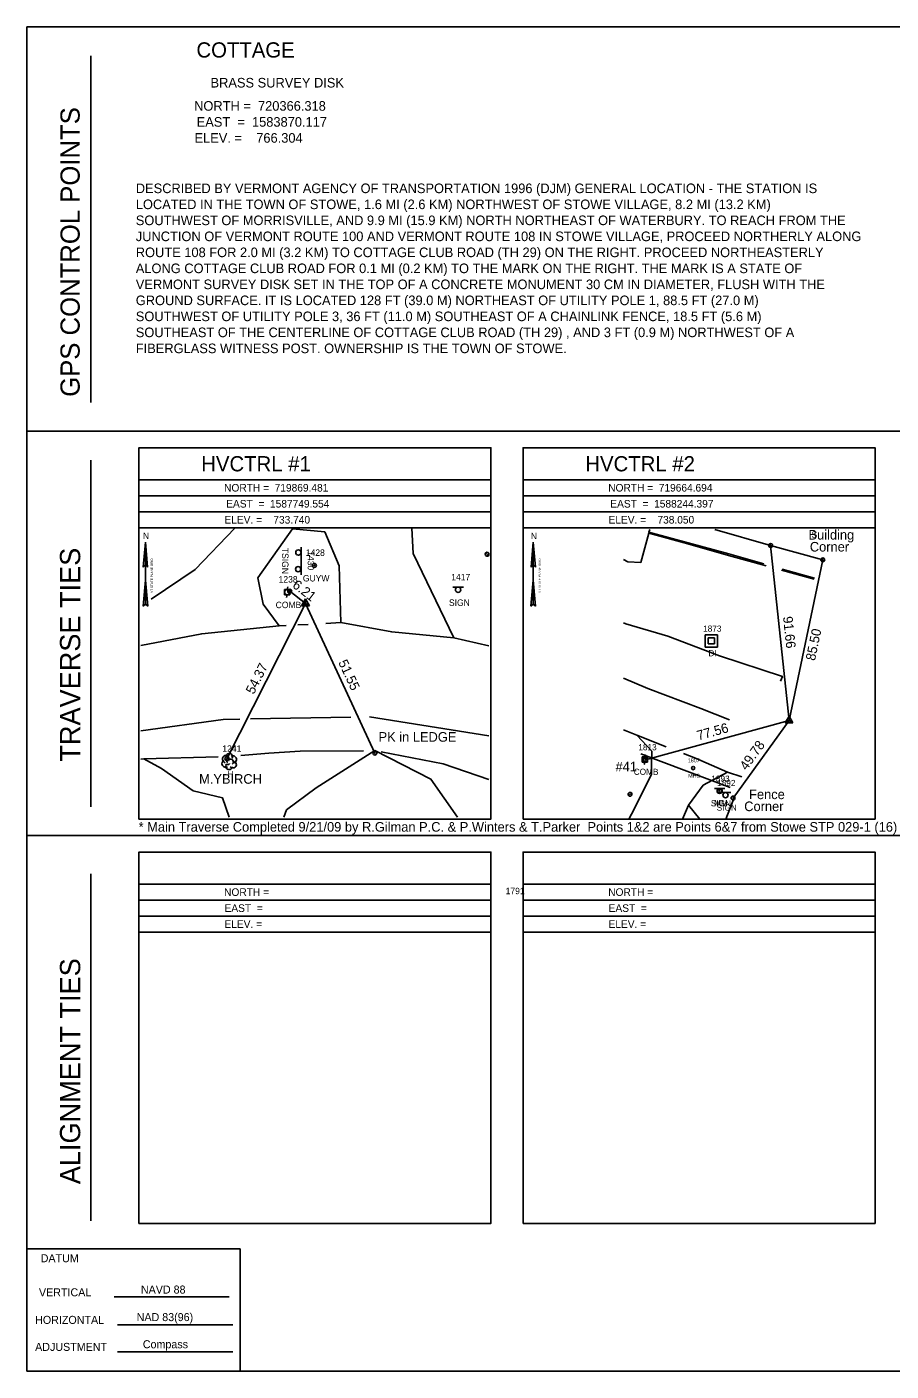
# Model space of a CAD drawing. Extents: x 1586965 to 1590952, y 716317 to 720029.
# Drawn here: x 1590312.2 to 1590582.2, y 716317.4 to 716737.4 of the extents above; entities that cross this region are included whole.
import ezdxf

# ---------------------------------------------------------------- set-up
doc = ezdxf.new("R2010")
doc.units = 0
for name, color, linetype in [('C_C', 7, 'Continuous'), ('CBP', 7, 'Continuous'), ('CPSM', 7, 'Continuous'), ('D_A', 7, 'Continuous'), ('D_I', 7, 'Continuous'), ('DCP', 7, 'Continuous'), ('Default', 7, 'Continuous'), ('DS', 7, 'Continuous'), ('L_A', 7, 'Continuous'), ('L_C', 7, 'Continuous'), ('L_I', 7, 'Continuous'), ('LARO', 7, 'Continuous'), ('LAWA', 7, 'Continuous'), ('LBC', 7, 'Continuous'), ('LFNC', 7, 'Continuous'), ('LTD', 7, 'Continuous'), ('NBL1', 7, 'Continuous'), ('NBL2', 7, 'Continuous'), ('NNA_P', 7, 'Continuous'), ('PET', 7, 'Continuous'), ('RDG', 7, 'Continuous'), ('RDP', 7, 'Continuous'), ('RSW', 7, 'Continuous'), ('S_A', 7, 'Continuous'), ('S_I', 7, 'Continuous'), ('SRM', 7, 'Continuous'), ('SSGN', 7, 'Continuous'), ('U_A', 7, 'Continuous'), ('U_C', 7, 'Continuous'), ('U_I', 7, 'Continuous'), ('UP', 7, 'Continuous'), ('UPGW', 7, 'Continuous'), ('USMH', 7, 'Continuous'), ('UWV', 7, 'Continuous')]:
    doc.layers.add(name, color=color, linetype=linetype)

msp = doc.modelspace()

# ---------------------------------------------------------------- linework, layer by layer
at = {"layer": 'CBP'}
for centre, radius in [((1590544.56, 716575.34), 0.6), ((1590544.56, 716575.34), 0.08), ((1590560.84, 716570.85), 0.6), ((1590560.84, 716570.85), 0.08), ((1590394.3, 716561.05), 0.625), ((1590394.3, 716561.05), 0.0833), ((1590374.69, 716508.7), 0.625), ((1590374.69, 716508.7), 0.0833), ((1590420.91, 716510.48), 0.625), ((1590420.91, 716510.48), 0.0833), ((1590505.42, 716508.32), 0.6), ((1590505.42, 716508.32), 0.08), ((1590532.82, 716496.43), 0.6), ((1590532.82, 716496.43), 0.08)]:
    msp.add_circle(centre, radius, dxfattribs=at)
at = {"layer": 'CPSM'}
for p, q in [((1590397.95, 716556.51), (1590399.2, 716558.68)), ((1590400.45, 716556.51), (1590399.2, 716558.68)), ((1590399.2, 716557.24), (1590399.2, 716558.68)), ((1590397.95, 716556.51), (1590399.2, 716557.24)), ((1590397.95, 716556.51), (1590400.45, 716556.51)), ((1590399.2, 716557.24), (1590399.2, 716557.24)), ((1590399.2, 716557.24), (1590400.45, 716556.51)), ((1590549.1, 716519.95), (1590550.3, 716522.03)), ((1590549.1, 716519.95), (1590550.3, 716520.64)), ((1590551.5, 716519.95), (1590550.3, 716522.03)), ((1590550.3, 716520.64), (1590550.3, 716522.03)), ((1590550.3, 716520.64), (1590550.3, 716520.64)), ((1590550.3, 716520.64), (1590551.5, 716519.95)), ((1590549.1, 716519.95), (1590551.5, 716519.95))]:
    msp.add_line(p, q, dxfattribs=at)
at = {"layer": 'DCP'}
msp.add_lwpolyline([(1590531.89, 716499.7), (1590504.01, 716510.18)], dxfattribs=at)
at = {"layer": 'Default'}
for p, q in [((1590550.3, 716520.64), (1590544.56, 716575.34)), ((1590560.84, 716570.85), (1590550.3, 716520.64)), ((1590399.2, 716557.24), (1590394.3, 716561.05)), ((1590374.69, 716508.7), (1590399.2, 716557.24)), ((1590399.2, 716557.24), (1590420.91, 716510.48)), ((1590505.42, 716508.32), (1590550.3, 716520.64)), ((1590550.3, 716520.64), (1590532.82, 716496.43))]:
    msp.add_line(p, q, dxfattribs=at)
at = {"layer": 'DS'}
for p, q in [((1590524.13, 716547.43), (1590527.97, 716547.43)), ((1590524.13, 716543.59), (1590524.13, 716547.43)), ((1590525.09, 716544.55), (1590525.09, 716546.47)), ((1590525.09, 716546.47), (1590527.01, 716546.47)), ((1590526.05, 716545.51), (1590526.05, 716545.51)), ((1590526.05, 716545.51), (1590526.05, 716545.51)), ((1590527.01, 716546.47), (1590527.01, 716544.55)), ((1590527.97, 716547.43), (1590527.97, 716543.59)), ((1590527.97, 716543.59), (1590524.13, 716543.59)), ((1590527.01, 716544.55), (1590525.09, 716544.55))]:
    msp.add_line(p, q, dxfattribs=at)
at = {"layer": 'LARO'}
for points in [[(1590347.78, 716508.6), (1590348.75, 716508.72), (1590354.22, 716505.67), (1590364.15, 716498.63), (1590373.3, 716496.5), (1590375.4, 716490.46)], [(1590392.42, 716490.46), (1590393.26, 716492.73), (1590402.53, 716499.63), (1590420.9, 716511.25), (1590438.43, 716502.34), (1590446.73, 716490.46)]]:
    msp.add_lwpolyline(points, dxfattribs=at)
at = {"layer": 'LAWA'}
for points in [[(1590347.78, 716508.6), (1590348.75, 716508.72), (1590371.97, 716509.25)], [(1590379.08, 716509.66), (1590387.8, 716510.41), (1590397.54, 716511.06), (1590417.31, 716511.22)], [(1590422.83, 716510.88), (1590442.3, 716507.07), (1590456.56, 716502.18)]]:
    msp.add_lwpolyline(points, dxfattribs=at)
at = {"layer": 'LBC'}
msp.add_line((1590544.56, 716575.34), (1590560.84, 716570.85), dxfattribs=at)
msp.add_lwpolyline([(1590527.08, 716580.33), (1590544.56, 716575.34)], dxfattribs=at)
at = {"layer": 'LFNC'}
msp.add_lwpolyline([(1590533.06, 716496.24), (1590530.56, 716489.86)], dxfattribs=at)
at = {"layer": 'LTD'}
msp.add_line((1590375.38, 716507.88), (1590375.38, 716507.88), dxfattribs=at)
msp.add_line((1590375.38, 716507.88), (1590375.38, 716507.88), dxfattribs=at)
msp.add_arc((1590375.42, 716509.31), 1.05, 335.5272, 180.9563, dxfattribs=at)
for centre, major_axis, ratio, start_param, end_param in [((1590374.29, 716507.17), (0.58, -1.04), 0.959034, 3.141593, 6.283185), ((1590374.58, 716508.54), (1.21, -0.51), 0.895232, 1.570796, 4.712389), ((1590375.17, 716508.34), (-0.208, -0.792), 0.645439, 3.141593, 6.283185), ((1590375.88, 716507.71), (-0.5, 0.667), 0.989748, 3.141593, 6.283185), ((1590376.38, 716507.04), (-1.09, 0.79), 0.841452, 1.570796, 4.712389), ((1590376.42, 716508.46), (-1.14, -0.48), 0.949671, 1.570796, 4.712389), ((1590375.38, 716506.38), (0.26, 1.06), 0.942809, 1.570796, 4.712389), ((1590374.92, 716507.13), (-0.625, -0.083), 0.423636, 0, 3.141593)]:
    msp.add_ellipse(centre, major_axis=major_axis, ratio=ratio, start_param=start_param, end_param=end_param, dxfattribs=at)
at = {"layer": 'NBL1'}
msp.add_lwpolyline([(1590312.19, 716317.36), (1590952.19, 716317.36), (1590952.19, 716737.36), (1590312.19, 716737.36)], close=True, dxfattribs=at)
at = {"layer": 'NBL2'}
for p, q in [((1590332.19, 716620.03), (1590332.19, 716728.36)), ((1590312.19, 716611.03), (1590952.19, 716611.03)), ((1590332.19, 716493.7), (1590332.19, 716602.03)), ((1590457.19, 716595.86), (1590347.19, 716595.86)), ((1590577.19, 716595.86), (1590467.19, 716595.86)), ((1590457.19, 716590.86), (1590347.19, 716590.86)), ((1590577.19, 716590.86), (1590467.19, 716590.86)), ((1590457.19, 716585.86), (1590347.19, 716585.86)), ((1590577.19, 716585.86), (1590467.19, 716585.86)), ((1590457.19, 716580.86), (1590347.19, 716580.86)), ((1590577.19, 716580.86), (1590467.19, 716580.86)), ((1590312.19, 716484.7), (1590952.19, 716484.7)), ((1590332.19, 716364.36), (1590332.19, 716472.7)), ((1590457.19, 716469.53), (1590347.19, 716469.53)), ((1590577.19, 716469.53), (1590467.19, 716469.53)), ((1590457.19, 716464.53), (1590347.19, 716464.53)), ((1590577.19, 716464.53), (1590467.19, 716464.53)), ((1590457.19, 716459.53), (1590347.19, 716459.53)), ((1590577.19, 716459.53), (1590467.19, 716459.53)), ((1590457.19, 716454.53), (1590347.19, 716454.53)), ((1590577.19, 716454.53), (1590467.19, 716454.53)), ((1590378.86, 716355.62), (1590312.19, 716355.62)), ((1590378.86, 716355.62), (1590378.86, 716317.36)), ((1590378.86, 716355.62), (1590378.86, 716317.36)), ((1590339.43, 716340.59), (1590375.43, 716340.56)), ((1590340.54, 716331.82), (1590376.54, 716331.82)), ((1590340.54, 716323.38), (1590376.54, 716323.35))]:
    msp.add_line(p, q, dxfattribs=at)
for points in [[(1590347.19, 716489.86), (1590457.19, 716489.86), (1590457.19, 716605.86), (1590347.19, 716605.86)], [(1590467.19, 716489.86), (1590577.19, 716489.86), (1590577.19, 716605.86), (1590467.19, 716605.86)], [(1590347.19, 716363.53), (1590457.19, 716363.53), (1590457.19, 716479.53), (1590347.19, 716479.53)], [(1590467.19, 716363.53), (1590577.19, 716363.53), (1590577.19, 716479.53), (1590467.19, 716479.53)]]:
    msp.add_lwpolyline(points, close=True, dxfattribs=at)
at = {"layer": 'NNA_P'}
for p, q in [((1590348.54, 716568.55), (1590349.23, 716576.34)), ((1590349.23, 716556.97), (1590349.23, 716576.34)), ((1590349.92, 716568.55), (1590349.23, 716576.34)), ((1590469.69, 716568.55), (1590470.39, 716576.34)), ((1590470.39, 716556.97), (1590470.39, 716576.34)), ((1590471.08, 716568.55), (1590470.39, 716576.34)), ((1590348.54, 716568.55), (1590349.23, 716569.31)), ((1590349.93, 716568.55), (1590349.23, 716569.31)), ((1590469.69, 716568.55), (1590470.39, 716569.31)), ((1590471.08, 716568.55), (1590470.39, 716569.31)), ((1590349.24, 716564.49), (1590348.51, 716556.33)), ((1590349.23, 716564.49), (1590349.95, 716556.33)), ((1590470.39, 716564.49), (1590469.67, 716556.33)), ((1590470.39, 716564.49), (1590471.11, 716556.33)), ((1590349.23, 716556.97), (1590348.51, 716556.33)), ((1590349.23, 716556.97), (1590349.95, 716556.33)), ((1590470.39, 716556.97), (1590469.67, 716556.33)), ((1590470.39, 716556.97), (1590471.11, 716556.33))]:
    msp.add_line(p, q, dxfattribs=at)
at = {"layer": 'PET'}
for points in [[(1590351.06, 716558.59), (1590364.78, 716567.86), (1590377.17, 716580.69)], [(1590391, 716550.19), (1590386.04, 716557.02), (1590384.37, 716565.19), (1590395.18, 716580.56), (1590405.23, 716579.6), (1590409.8, 716568.93), (1590410.24, 716551.25)], [(1590432.44, 716580.69), (1590432.88, 716572.84), (1590445.62, 716546.49)], [(1590347.78, 716544.1), (1590366.85, 716547.73), (1590391, 716550.19), (1590393.23, 716550.32)], [(1590396.85, 716550.51), (1590400.06, 716550.69)], [(1590405.57, 716550.99), (1590410.24, 716551.25), (1590426.21, 716548.33), (1590445.62, 716546.49), (1590456.56, 716543.97)], [(1590498.55, 716533.92), (1590506.19, 716530.66), (1590522.72, 716524.42), (1590531.67, 716520.9)], [(1590347.78, 716517.39), (1590373.53, 716520.96), (1590378.69, 716521.06)], [(1590382.05, 716521.12), (1590413.4, 716521.7)], [(1590419.24, 716521.8), (1590456.56, 716515.85)], [(1590498.55, 716517.77), (1590502.72, 716516.03), (1590511.9, 716512.47)], [(1590502.72, 716516.03), (1590507.43, 716511.07), (1590507.26, 716503.53), (1590501.04, 716491.38), (1590500.29, 716489.86)], [(1590517.32, 716510.36), (1590521.07, 716508.9), (1590531.09, 716504.54), (1590535.58, 716503)], [(1590517.03, 716489.86), (1590518.92, 716494.15), (1590523.51, 716500.47), (1590531.09, 716504.54)]]:
    msp.add_lwpolyline(points, dxfattribs=at)
at = {"layer": 'RDG'}
for points in [[(1590498.55, 716570.92), (1590499.93, 716570.23), (1590504.03, 716570.03)], [(1590498.55, 716551.11), (1590499.34, 716550.88)], [(1590522.42, 716489.86), (1590518.92, 716494.15)]]:
    msp.add_lwpolyline(points, dxfattribs=at)
at = {"layer": 'RDP'}
for points in [[(1590504.03, 716570.03), (1590506.46, 716579.21), (1590518.69, 716575.88), (1590531.36, 716572.16), (1590543.17, 716568.94)], [(1590547.99, 716567.62), (1590558.2, 716564.83)], [(1590499.34, 716550.88), (1590512.45, 716547), (1590528.53, 716540.88), (1590548.23, 716534.44), (1590547.61, 716532.89)]]:
    msp.add_lwpolyline(points, dxfattribs=at)
at = {"layer": 'RSW'}
for points in [[(1590506.78, 716580.33), (1590506.49, 716579.44), (1590518.76, 716576.18), (1590531.47, 716572.69), (1590542.47, 716569.59)], [(1590548.2, 716567.98), (1590558.29, 716565.14)]]:
    msp.add_lwpolyline(points, dxfattribs=at)
at = {"layer": 'SRM'}
msp.add_lwpolyline([(1590528.02, 716499.24), (1590529.22, 716499.24), (1590529.22, 716498.04), (1590528.02, 716498.04)], close=True, dxfattribs=at)
msp.add_circle((1590528.62, 716498.64), 0.08, dxfattribs=at)
at = {"layer": 'SSGN'}
for p, q in [((1590397.84, 716574.8), (1590397.84, 716566.2)), ((1590396.94, 716570.77), (1590396.94, 716570.77)), ((1590445.27, 716562.32), (1590448.6, 716562.32)), ((1590446.92, 716561.49), (1590446.92, 716561.49)), ((1590527.05, 716499.45), (1590530.25, 716499.45)), ((1590528.63, 716498.65), (1590528.63, 716498.65)), ((1590528.87, 716498.1), (1590532.07, 716498.1)), ((1590530.45, 716497.3), (1590530.45, 716497.3))]:
    msp.add_line(p, q, dxfattribs=at)
for centre, radius in [((1590397.01, 716573.13), 0.833), ((1590396.94, 716567.92), 0.833), ((1590446.92, 716561.49), 0.833), ((1590528.63, 716498.65), 0.8), ((1590530.45, 716497.3), 0.8)]:
    msp.add_circle(centre, radius, dxfattribs=at)
at = {"layer": 'UP'}
for p, q in [((1590393.77, 716562.42), (1590393.52, 716561.59)), ((1590392.69, 716559.92), (1590392.69, 716561.59)), ((1590392.69, 716561.59), (1590394.36, 716561.59)), ((1590394.36, 716559.92), (1590392.69, 716559.92)), ((1590393.27, 716559.09), (1590393.52, 716559.92)), ((1590393.52, 716560.75), (1590393.52, 716560.75)), ((1590394.36, 716561.59), (1590394.36, 716559.92)), ((1590504.47, 716507.66), (1590504.47, 716509.26)), ((1590504.47, 716509.26), (1590506.07, 716509.26)), ((1590506.07, 716507.66), (1590504.47, 716507.66)), ((1590505.03, 716506.86), (1590505.27, 716507.66)), ((1590505.51, 716510.06), (1590505.27, 716509.26)), ((1590505.27, 716508.46), (1590505.27, 716508.46)), ((1590506.07, 716509.26), (1590506.07, 716507.66))]:
    msp.add_line(p, q, dxfattribs=at)
for centre, radius in [((1590393.52, 716560.75), 0.833), ((1590505.27, 716508.46), 0.8)]:
    msp.add_circle(centre, radius, dxfattribs=at)
at = {"layer": 'UPGW'}
for centre, radius in [((1590402.02, 716569.09), 0.625), ((1590402.02, 716569.09), 0.0833), ((1590500.64, 716497.6), 0.6), ((1590500.64, 716497.6), 0.08)]:
    msp.add_circle(centre, radius, dxfattribs=at)
at = {"layer": 'USMH'}
for p, q in [((1590520.35, 716505.78), (1590520.35, 716505.78)), ((1590520.85, 716505.78), (1590520.85, 716505.78))]:
    msp.add_line(p, q, dxfattribs=at)
msp.add_circle((1590520.35, 716505.78), 0.5, dxfattribs=at)
at = {"layer": 'UWV'}
msp.add_line((1590456.56, 716572.28), (1590456.56, 716572.91), dxfattribs=at)
msp.add_circle((1590456.02, 716572.59), 0.0833, dxfattribs=at)
msp.add_arc((1590456.02, 716572.59), 0.625, 30.2636, 329.7364, dxfattribs=at)

# ---------------------------------------------------------------- texts
at = {"layer": 'C_C'}
for s, p in [('Building', (1590556.39, 716577.18)), ('Corner', (1590556.8, 716573.43)), ('PK in LEDGE ', (1590422.07, 716514.02)), ('Fence', (1590537.83, 716496.08)), ('Corner', (1590536.31, 716492.33))]:
    msp.add_text(s, height=3, dxfattribs=at).set_placement(p)
at = {"layer": 'D_A'}
msp.add_text('DI', height=1.92, dxfattribs=at).set_placement((1590525.14, 716540.71))
at = {"layer": 'D_I'}
msp.add_text('1873', height=1.92, dxfattribs=at).set_placement((1590523.47, 716548.39))
at = {"layer": 'Default'}
for s, p in [('DESCRIBED BY VERMONT AGENCY OF TRANSPORTATION 1996 (DJM) GENERAL LOCATION - THE STATION IS ', (1590346.22, 716685.42)), ('LOCATED IN THE TOWN OF STOWE, 1.6 MI (2.6 KM) NORTHWEST OF STOWE VILLAGE, 8.2 MI (13.2 KM) ', (1590346.22, 716680.42)), ('SOUTHWEST OF MORRISVILLE, AND 9.9 MI (15.9 KM) NORTH NORTHEAST OF WATERBURY. TO REACH FROM THE ', (1590346.22, 716675.42)), ('JUNCTION OF VERMONT ROUTE 100 AND VERMONT ROUTE 108 IN STOWE VILLAGE, PROCEED NORTHERLY ALONG ', (1590346.22, 716670.42)), ('ROUTE 108 FOR 2.0 MI (3.2 KM) TO COTTAGE CLUB ROAD (TH 29) ON THE RIGHT. PROCEED NORTHEASTERLY ', (1590346.22, 716665.42)), ('ALONG COTTAGE CLUB ROAD FOR 0.1 MI (0.2 KM) TO THE MARK ON THE RIGHT. THE MARK IS A STATE OF ', (1590346.22, 716660.42)), ('VERMONT SURVEY DISK SET IN THE TOP OF A CONCRETE MONUMENT 30 CM IN DIAMETER, FLUSH WITH THE ', (1590346.22, 716655.42)), ('GROUND SURFACE. IT IS LOCATED 128 FT (39.0 M) NORTHEAST OF UTILITY POLE 1, 88.5 FT (27.0 M) ', (1590346.22, 716650.42)), ('SOUTHWEST OF UTILITY POLE 3, 36 FT (11.0 M) SOUTHEAST OF A CHAINLINK FENCE, 18.5 FT (5.6 M) ', (1590346.22, 716645.42)), ('SOUTHEAST OF THE CENTERLINE OF COTTAGE CLUB ROAD (TH 29) , AND 3 FT (0.9 M) NORTHWEST OF A ', (1590346.22, 716640.42)), ('FIBERGLASS WITNESS POST. OWNERSHIP IS THE TOWN OF STOWE. ', (1590346.22, 716635.42)), ('* Main Traverse Completed 9/21/09 by R.Gilman P.C. & P.Winters & T.Parker  Points 1&2 are Points 6&7 from Stowe STP 029-1 (16) "93b059"', (1590347.1, 716485.91))]:
    msp.add_text(s, height=3, dxfattribs=at).set_placement(p)
for s, rotation, p in [('6.21', 322.105, (1590394.91, 716562.47)), ('91.66', 275.9884, (1590548.41, 716553.04)), ('85.50', 78.144, (1590558.39, 716539.16)), ('54.37', 63.2073, (1590383.07, 716528.63)), ('51.55', 294.91, (1590409.41, 716538.82)), ('77.56', 15.3554, (1590521.96, 716514.41)), ('49.78', 54.1729, (1590537.05, 716504.85))]:
    msp.add_text(s, height=3, rotation=rotation, dxfattribs=at).set_placement(p)
at = {"layer": 'L_A'}
for s, p in [('S', (1590557.34, 716577.73)), ('H', (1590374.81, 716502.88))]:
    msp.add_text(s, height=2, dxfattribs=at).set_placement(p)
at = {"layer": 'L_C'}
msp.add_text('M.YBIRCH', height=3, dxfattribs=at).set_placement((1590366, 716500.88))
at = {"layer": 'L_I'}
msp.add_text('1241', height=2, dxfattribs=at).set_placement((1590373.25, 716510.88))
at = {"layer": 'NBL2'}
for s, height, p in [('      COTTAGE      ', 4.75, (1590354.58, 716727.79)), ('BRASS SURVEY DISK', 3, (1590369.57, 716718.42)), ('NORTH =  720366.318 ', 3, (1590364.45, 716711.17)), ('EAST  =  1583870.117', 3, (1590365.24, 716706.17)), ('ELEV. =    766.304  ', 3, (1590364.56, 716701.17)), ('     HVCTRL #1     ', 4.75, (1590357.84, 716598.49)), ('     HVCTRL #2     ', 4.75, (1590477.84, 716598.49)), ('NORTH =  719869.481 ', 2.375, (1590373.81, 716592.18)), ('NORTH =  719664.694 ', 2.375, (1590493.81, 716592.18)), ('EAST  =  1587749.554', 2.375, (1590374.47, 716587.18)), ('EAST  =  1588244.397', 2.375, (1590494.47, 716587.18)), ('ELEV. =    733.740  ', 2.375, (1590373.92, 716582.18)), ('ELEV. =    738.050  ', 2.375, (1590493.92, 716582.18)), ('NORTH =             ', 2.375, (1590373.81, 716465.84)), ('NORTH =             ', 2.375, (1590493.81, 716465.84)), ('EAST  =             ', 2.375, (1590373.95, 716460.84)), ('EAST  =             ', 2.375, (1590493.95, 716460.84)), ('ELEV. =             ', 2.375, (1590373.92, 716455.84)), ('ELEV. =             ', 2.375, (1590493.92, 716455.84)), ('DATUM', 2.5, (1590316.51, 716351.38)), ('  NAVD 88 ', 2.5, (1590345.96, 716341.6)), ('NAD 83(96) ', 2.5, (1590346.5, 716332.99)), ('HORIZONTAL', 2.5, (1590314.77, 716332.12)), ('  Compass ', 2.5, (1590346.56, 716324.51)), ('ADJUSTMENT', 2.5, (1590314.77, 716323.68))]:
    msp.add_text(s, height=height, dxfattribs=at).set_placement(p)
for s, height, rotation, p in [('GPS CONTROL POINTS', 6, 90, (1590328.69, 716621.78)), ('TRAVERSE TIES', 6.3332, 90, (1590328.86, 716507.8)), ('ALIGNMENT TIES', 6.3332, 90, (1590328.86, 716375.77)), ('VERTICAL', 2.5, 0.1439, (1590315.97, 716340.71))]:
    msp.add_text(s, height=height, rotation=rotation, dxfattribs=at).set_placement(p)
at = {"layer": 'NNA_P'}
for p in [(1590348.47, 716577.35), (1590469.63, 716577.35)]:
    msp.add_text('N', height=1.97, dxfattribs=at).set_placement(p)
for p in [(1590351.58, 716560.53), (1590472.74, 716560.53)]:
    msp.add_text('VT STATE PLANE GRID', height=0.7, rotation=90.0204, dxfattribs=at).set_placement(p)
at = {"layer": 'S_A'}
msp.add_text('TSIGN', height=2, rotation=270, dxfattribs=at).set_placement((1590391.92, 716574.6))
for s, height, p in [('SIGN', 2, (1590444.05, 716556.47)), ('SIGN', 1.92, (1590525.88, 716493.83)), ('MM', 1.92, (1590526.88, 716493.84)), ('SIGN', 1.92, (1590527.7, 716492.48))]:
    msp.add_text(s, height=height, dxfattribs=at).set_placement(p)
at = {"layer": 'S_I'}
msp.add_text('1430', height=2, rotation=270, dxfattribs=at).set_placement((1590399.92, 716573.56))
for s, height, p in [('1417', 2, (1590444.77, 716564.47)), ('1893', 1.92, (1590526.03, 716501.51)), ('1893', 1.92, (1590526.04, 716501.52)), ('1892', 1.92, (1590527.85, 716500.16))]:
    msp.add_text(s, height=height, dxfattribs=at).set_placement(p)
at = {"layer": 'U_A'}
for s, height, p in [('GUYW', 2, (1590398.41, 716564.09)), ('COMB', 2, (1590389.91, 716555.75)), ('COMB', 1.92, (1590501.8, 716503.66)), ('MHS', 1.2, (1590518.8, 716502.78))]:
    msp.add_text(s, height=height, dxfattribs=at).set_placement(p)
at = {"layer": 'U_C'}
msp.add_text('#41', height=3, dxfattribs=at).set_placement((1590496.1, 716504.74))
at = {"layer": 'U_I'}
for s, height, p in [('1428', 2, (1590399.33, 716572.09)), ('1238', 2, (1590390.83, 716563.75)), ('1813', 1.92, (1590503.23, 716511.34)), ('1807', 1.2, (1590518.69, 716507.58)), ('1791', 2, (1590461.76, 716466.38))]:
    msp.add_text(s, height=height, dxfattribs=at).set_placement(p)

doc.saveas('drawing.dxf')
